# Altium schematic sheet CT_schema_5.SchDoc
size 283 x 147 mm
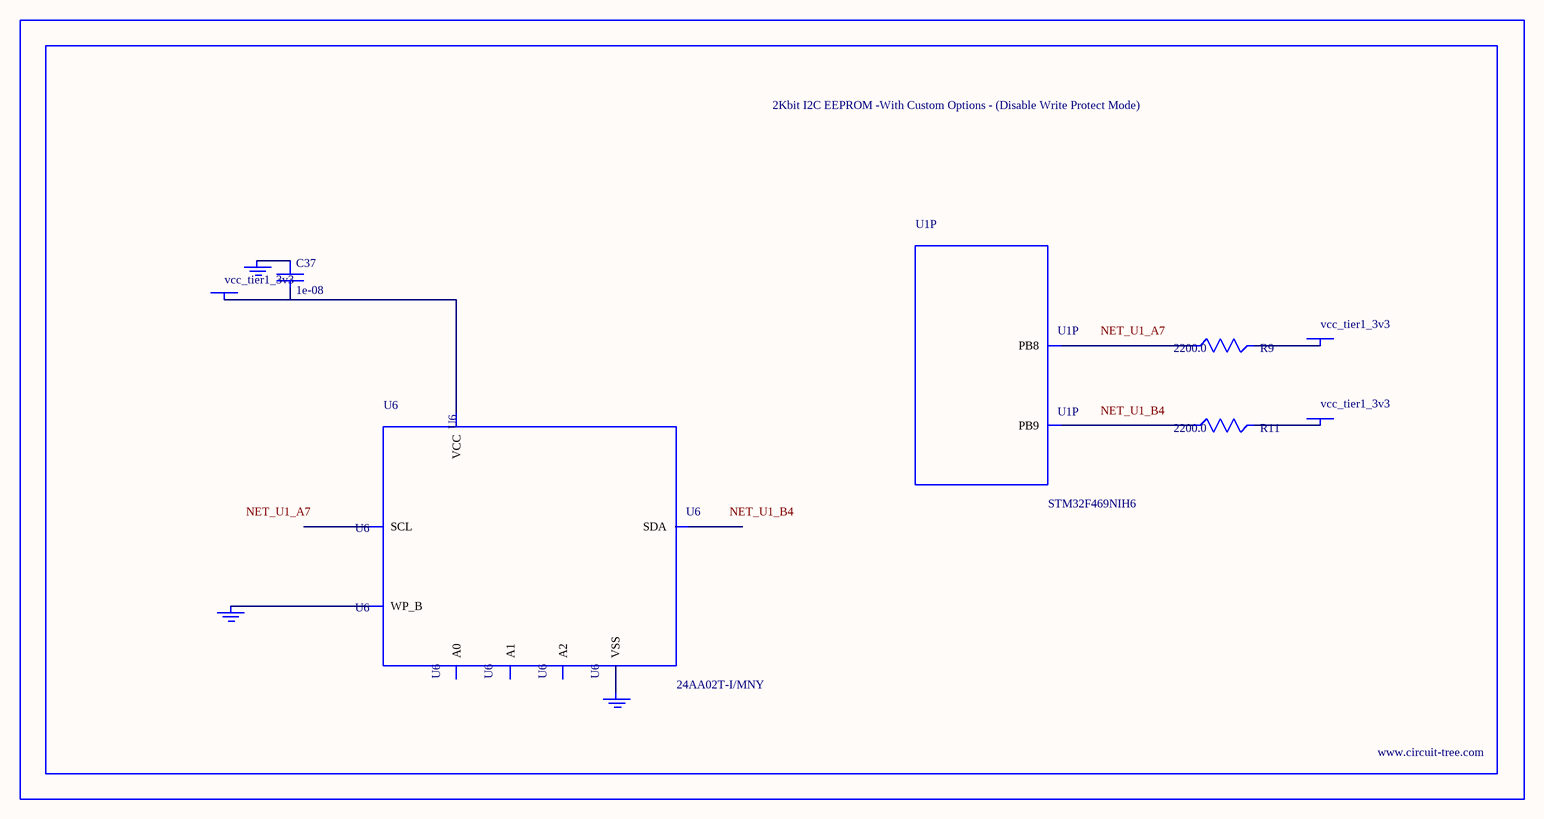
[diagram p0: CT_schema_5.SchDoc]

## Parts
BORDER4  (no value)
C37  1e-08  [C0402]
GND_INSTANCE_4_0  (no value)
GND_INSTANCE_4_1  (no value)
GND_INSTANCE_4_2  (no value)
POWER_INSTANCE_4_0  vcc_tier1_3v3
POWER_INSTANCE_4_1  vcc_tier1_3v3
POWER_INSTANCE_4_2  vcc_tier1_3v3
R9  2200.0  [R0603]
R11  2200.0  [R0603]
U1  STM32F469NIH6  [TFBGA216]  (part P of 17)
U6  24AA02T-I/MNY  [TDFN-8/6MM]

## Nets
NetC37_1: C37.1 GND_INSTANCE_4_1.0(GND)
NetC37_2: C37.2 POWER_INSTANCE_4_0.0(PWR) U6.8(VCC)
NetGND_INSTANCE_4_0_0: GND_INSTANCE_4_0.0(GND) U6.7(WP_B)
NetGND_INSTANCE_4_2_0: GND_INSTANCE_4_2.0(GND) U6.4(VSS)
NetPOWER_INSTANCE_4_1_0: POWER_INSTANCE_4_1.0(PWR) R9.2
NetPOWER_INSTANCE_4_2_0: POWER_INSTANCE_4_2.0(PWR) R11.2
NetR9_1: R9.1 U1.A7(PB8)
NetR11_1: R11.1 U1.B4(PB9)

Not connected (* = marked no-connect by the designer): U6 1(A0) 2(A1) 3(A2) 5(SDA) 6(SCL)

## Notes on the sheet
- Labels drawn without touching a wire or pin: NET_U1_A7, NET_U1_B4

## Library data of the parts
BORDER4 = BORDER_PAGE4
C37 = C0402C103K3RAC
GND_INSTANCE_4_0-GND_INSTANCE_4_2 = GND
POWER_INSTANCE_4_0-POWER_INSTANCE_4_2 = PWR
R9 R11 = RC0603JR-072K2L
